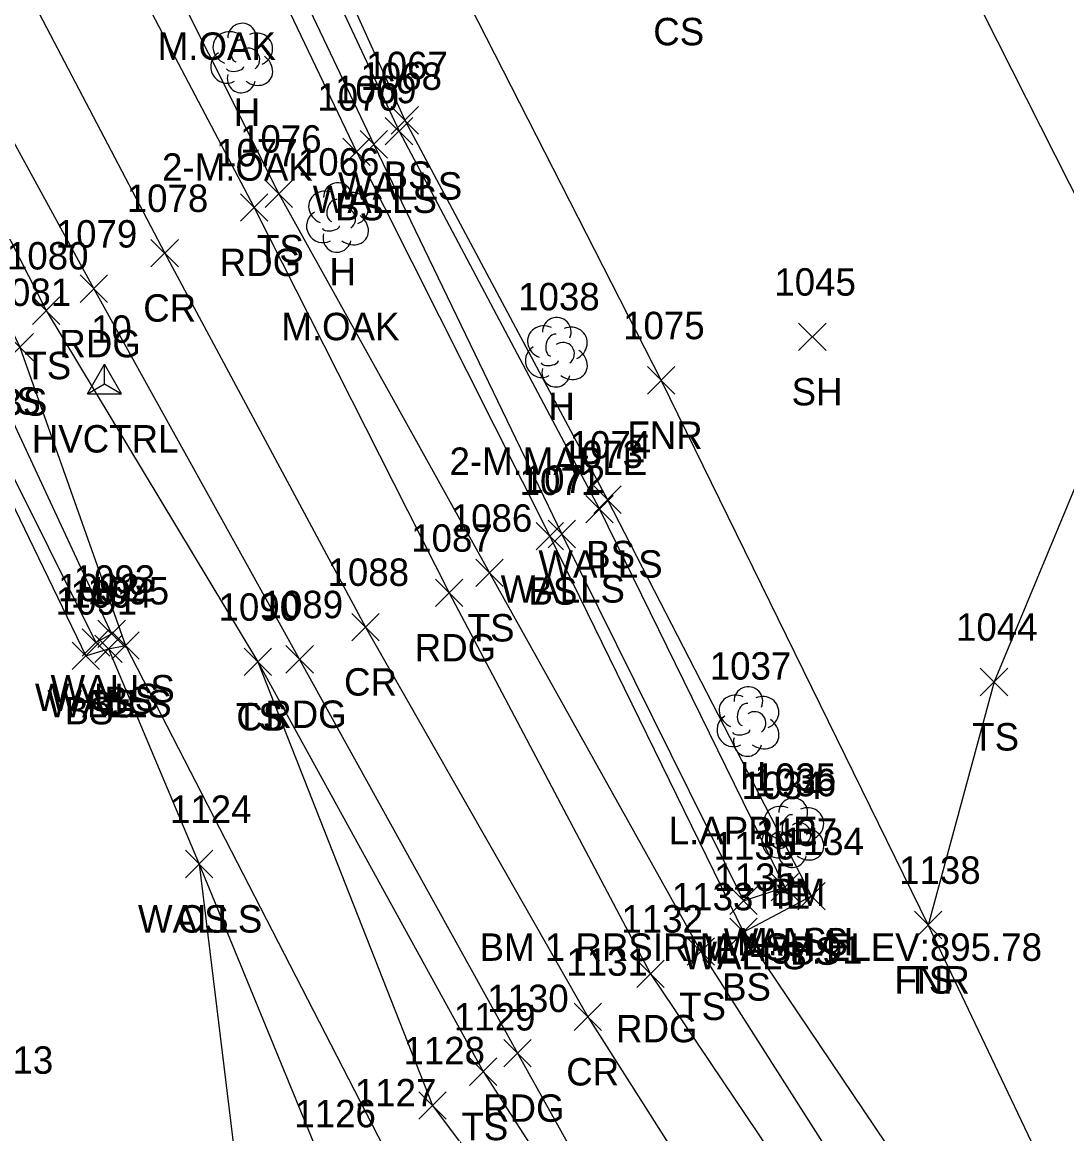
# Model space of a CAD drawing. Extents: x 1441651 to 1442140, y 243798 to 245625.
# Drawn here: x 1441948.7 to 1442024.9, y 245501.1 to 245582.1 of the extents above; entities that cross this region are included whole.
import ezdxf

# ---------------------------------------------------------------- set-up
doc = ezdxf.new("R2010")
doc.units = 0
for name, color, linetype in [('C_A', 7, 'Continuous'), ('C_C', 7, 'Continuous'), ('C_I', 7, 'Continuous'), ('CBP', 7, 'Continuous'), ('CPBM', 7, 'Continuous'), ('CPSM', 7, 'Continuous'), ('L_A', 7, 'Continuous'), ('L_C', 7, 'Continuous'), ('L_I', 7, 'Continuous'), ('L_TIC', 7, 'Continuous'), ('LELB', 7, 'Continuous'), ('LFNC', 7, 'Continuous'), ('LSOGP', 7, 'Continuous'), ('LTD', 7, 'Continuous'), ('LWS', 7, 'Continuous'), ('P_A', 7, 'Continuous'), ('P_I', 7, 'Continuous'), ('P_TIC', 7, 'Continuous'), ('PEU', 7, 'Continuous'), ('PRC', 7, 'Continuous')]:
    doc.layers.add(name, color=color, linetype=linetype)

msp = doc.modelspace()

# ---------------------------------------------------------------- linework, layer by layer
at = {"layer": 'CBP'}
for radius in [0.625, 0.0833]:
    msp.add_circle((1442003.914, 245522.51), radius, dxfattribs=at)
at = {"layer": 'CPBM'}
for p, q in [((1442004.413, 245522.213), (1442004.413, 245523.213)), ((1442004.413, 245523.213), (1442005.413, 245523.213)), ((1442005.413, 245523.213), (1442005.413, 245522.213)), ((1442004.916, 245522.713), (1442004.916, 245522.713)), ((1442004.916, 245522.713), (1442004.916, 245522.713)), ((1442005.413, 245522.213), (1442004.413, 245522.213))]:
    msp.add_line(p, q, dxfattribs=at)
at = {"layer": 'CPSM'}
for p, q in [((1441953.421, 245555.052), (1441954.671, 245557.218)), ((1441955.921, 245555.052), (1441954.671, 245557.218)), ((1441954.671, 245555.774), (1441954.671, 245557.218)), ((1441953.421, 245555.052), (1441954.671, 245555.774)), ((1441954.671, 245555.774), (1441954.671, 245555.774)), ((1441954.671, 245555.774), (1441955.921, 245555.052)), ((1441953.421, 245555.052), (1441955.921, 245555.052))]:
    msp.add_line(p, q, dxfattribs=at)
at = {"layer": 'L_TIC'}
for points in [[(1441975.585, 245573.997), (1441977.585, 245575.997)], [(1441977.585, 245573.997), (1441975.585, 245575.997)], [(1441975.154, 245573.213), (1441977.154, 245575.213)], [(1441977.154, 245573.213), (1441975.154, 245575.213)], [(1441972.054, 245571.702), (1441974.054, 245573.702)], [(1441974.054, 245571.702), (1441972.054, 245573.702)], [(1441973.311, 245572.242), (1441975.311, 245574.242)], [(1441975.311, 245572.242), (1441973.311, 245574.242)], [(1441966.384, 245568.64), (1441968.384, 245570.64)], [(1441968.384, 245568.64), (1441966.384, 245570.64)], [(1441949.412, 245560.12), (1441951.412, 245562.12)], [(1441951.412, 245560.12), (1441949.412, 245562.12)], [(1442005.303, 245558.212), (1442007.303, 245560.212)], [(1442007.303, 245558.212), (1442005.303, 245560.212)], [(1441947.491, 245557.459), (1441949.491, 245559.459)], [(1441949.491, 245557.459), (1441947.491, 245559.459)], [(1441994.271, 245555.037), (1441996.271, 245557.037)], [(1441996.271, 245555.037), (1441994.271, 245557.037)], [(1441990.363, 245546.336), (1441992.363, 245548.336)], [(1441992.363, 245546.336), (1441990.363, 245548.336)], [(1441989.775, 245545.648), (1441991.775, 245547.648)], [(1441991.775, 245545.648), (1441989.775, 245547.648)], [(1441986.155, 245543.678), (1441988.155, 245545.678)], [(1441988.155, 245543.678), (1441986.155, 245545.678)], [(1441987.023, 245543.831), (1441989.023, 245545.831)], [(1441989.023, 245543.831), (1441987.023, 245545.831)], [(1441981.753, 245540.997), (1441983.753, 245542.997)], [(1441983.753, 245540.997), (1441981.753, 245542.997)], [(1441953.048, 245535.929), (1441955.048, 245537.929)], [(1441955.048, 245535.929), (1441953.048, 245537.929)], [(1441954.19, 245536.551), (1441956.19, 245538.551)], [(1441956.19, 245536.551), (1441954.19, 245538.551)], [(1441954.19, 245536.551), (1441956.19, 245538.551)], [(1441956.19, 245536.551), (1441954.19, 245538.551)], [(1441953.957, 245535.46), (1441955.957, 245537.46)], [(1441955.957, 245535.46), (1441953.957, 245537.46)], [(1441953.957, 245535.46), (1441955.957, 245537.46)], [(1441955.957, 245535.46), (1441953.957, 245537.46)], [(1441955.206, 245535.697), (1441957.206, 245537.697)], [(1441957.206, 245535.697), (1441955.206, 245537.697)], [(1441955.206, 245535.697), (1441957.206, 245537.697)], [(1441957.206, 245535.697), (1441955.206, 245537.697)], [(1441952.315, 245534.956), (1441954.315, 245536.956)], [(1441954.315, 245534.956), (1441952.315, 245536.956)], [(1441964.846, 245534.511), (1441966.846, 245536.511)], [(1441966.846, 245534.511), (1441964.846, 245536.511)], [(1441964.846, 245534.511), (1441966.846, 245536.511)], [(1441966.846, 245534.511), (1441964.846, 245536.511)], [(1442018.558, 245533.046), (1442020.558, 245535.046)], [(1442020.558, 245533.046), (1442018.558, 245535.046)], [(1442018.558, 245533.046), (1442020.558, 245535.046)], [(1442020.558, 245533.046), (1442018.558, 245535.046)], [(1441960.569, 245519.773), (1441962.569, 245521.773)], [(1441962.569, 245519.773), (1441960.569, 245521.773)], [(1441960.569, 245519.773), (1441962.569, 245521.773)], [(1441962.569, 245519.773), (1441960.569, 245521.773)], [(1442003.296, 245518.092), (1442005.296, 245520.092)], [(1442005.296, 245518.092), (1442003.296, 245520.092)], [(1442003.296, 245518.092), (1442005.296, 245520.092)], [(1442005.296, 245518.092), (1442003.296, 245520.092)], [(1442005.245, 245517.425), (1442007.245, 245519.425)], [(1442007.245, 245517.425), (1442005.245, 245519.425)], [(1442000.283, 245517.1), (1442002.283, 245519.1)], [(1442002.283, 245517.1), (1442000.283, 245519.1)], [(1442000.278, 245514.813), (1442002.278, 245516.813)], [(1442002.278, 245514.813), (1442000.278, 245516.813)], [(1442000.278, 245514.813), (1442002.278, 245516.813)], [(1442002.278, 245514.813), (1442000.278, 245516.813)], [(1442013.76, 245515.326), (1442015.76, 245517.326)], [(1442015.76, 245515.326), (1442013.76, 245517.326)], [(1442013.76, 245515.326), (1442015.76, 245517.326)], [(1442015.76, 245515.326), (1442013.76, 245517.326)], [(1441997.178, 245513.398), (1441999.178, 245515.398)], [(1441999.178, 245513.398), (1441997.178, 245515.398)], [(1441981.294, 245504.635), (1441983.294, 245506.635)], [(1441983.294, 245504.635), (1441981.294, 245506.635)], [(1441977.601, 245502.173), (1441979.601, 245504.173)], [(1441979.601, 245502.173), (1441977.601, 245504.173)]]:
    msp.add_lwpolyline(points, dxfattribs=at)
at = {"layer": 'LELB'}
for points in [[(1441962.421, 245606.26), (1441976.585, 245574.997), (1441991.363, 245547.336), (1442006.245, 245518.425), (1442001.278, 245515.813)], [(1441958.143, 245603.853), (1441973.054, 245572.702), (1441987.155, 245544.678), (1442001.278, 245515.813), (1442017.222, 245492.134), (1442028.726, 245467.165), (1442040.19, 245452.018), (1442046.602, 245443.334), (1442055.536, 245439.064), (1442059.345, 245437.756)], [(1441951.999, 245600.361), (1441967.384, 245569.64), (1441982.753, 245541.997), (1441998.178, 245514.398), (1442013.668, 245490.085), (1442025.646, 245464.596), (1442043.563, 245442.549), (1442056.061, 245427.98)], [(1441935.553, 245590.253), (1441950.412, 245561.12), (1441965.846, 245535.511), (1441982.294, 245505.635), (1441993.222, 245488.677)], [(1441933.718, 245589.334), (1441948.491, 245558.459), (1441956.206, 245536.697), (1441975.054, 245500.102), (1441979.331, 245493.092), (1441987.533, 245478.538), (1441986.565, 245474.385), (1441981.273, 245469.984), (1441969.099, 245476.162)], [(1441929.024, 245587.875), (1441942.939, 245557.338), (1441953.315, 245535.956), (1441954.957, 245536.46), (1441956.206, 245536.697)], [(1442030.344, 245559.965), (1442019.558, 245534.046)], [(1441965.846, 245535.511), (1441978.601, 245503.173), (1441992.694, 245484.345)], [(1442019.558, 245534.046), (1442014.76, 245516.326)], [(1441961.569, 245520.773), (1441964.796, 245494.494), (1441969.099, 245476.162)]]:
    msp.add_lwpolyline(points, dxfattribs=at)
at = {"layer": 'LFNC'}
msp.add_lwpolyline([(1441970.219, 245607.538), (1441978.861, 245588.199), (1441995.271, 245556.037), (1442014.76, 245516.326), (1442024.694, 245495.45), (1442031.67, 245481.036), (1442036.993, 245470.06), (1442042.58, 245457.764), (1442044.092, 245455.722)], dxfattribs=at)
at = {"layer": 'LSOGP'}
msp.add_lwpolyline([(1442030.344, 245559.965), (1442014.55, 245591.18)], dxfattribs=at)
at = {"layer": 'LTD'}
for p, q in [((1441964.664, 245579.589), (1441964.664, 245579.589)), ((1441964.664, 245579.589), (1441964.664, 245579.589)), ((1441971.648, 245567.963), (1441971.648, 245567.963)), ((1441971.648, 245567.963), (1441971.648, 245567.963)), ((1441987.616, 245558.142), (1441987.616, 245558.142)), ((1441987.616, 245558.142), (1441987.616, 245558.142)), ((1442001.591, 245531.216), (1442001.591, 245531.216)), ((1442001.591, 245531.216), (1442001.591, 245531.216)), ((1442004.863, 245523.11), (1442004.863, 245523.11)), ((1442004.863, 245523.11), (1442004.863, 245523.11))]:
    msp.add_line(p, q, dxfattribs=at)
for centre in [(1441964.71, 245581.023), (1441971.695, 245569.397), (1441987.663, 245559.575), (1442001.637, 245532.65), (1442004.909, 245524.544)]:
    msp.add_arc(centre, 1.047, 335.52715, 180.95627, dxfattribs=at)
for centre, major_axis, ratio, start_param, end_param in [((1441963.872, 245580.256), (1.21, -0.512), 0.895232, 1.570796, 4.712389), ((1441964.455, 245580.047), (-0.208, -0.792), 0.645439, 3.141593, 6.283185), ((1441965.705, 245580.173), (-1.141, -0.483), 0.949671, 1.570796, 4.712389), ((1441965.164, 245579.423), (-0.5, 0.667), 0.989748, 3.141593, 6.283185), ((1441963.58, 245578.881), (0.584, -1.042), 0.959034, 3.141593, 6.283185), ((1441965.664, 245578.756), (-1.09, 0.792), 0.841452, 1.570796, 4.712389), ((1441964.664, 245578.089), (0.265, 1.061), 0.942809, 1.570796, 4.712389), ((1441964.205, 245578.839), (-0.625, -0.083), 0.423636, 0, 3.141593), ((1441970.856, 245568.63), (1.21, -0.512), 0.895232, 1.570796, 4.712389), ((1441972.69, 245568.547), (-1.141, -0.483), 0.949671, 1.570796, 4.712389), ((1441971.44, 245568.422), (-0.208, -0.792), 0.645439, 3.141593, 6.283185), ((1441972.148, 245567.797), (-0.5, 0.667), 0.989748, 3.141593, 6.283185), ((1441970.565, 245567.255), (0.584, -1.042), 0.959034, 3.141593, 6.283185), ((1441972.648, 245567.13), (-1.09, 0.792), 0.841452, 1.570796, 4.712389), ((1441971.19, 245567.213), (-0.625, -0.083), 0.423636, 0, 3.141593), ((1441971.648, 245566.463), (0.265, 1.061), 0.942809, 1.570796, 4.712389), ((1441986.824, 245558.808), (1.21, -0.512), 0.895232, 1.570796, 4.712389), ((1441988.657, 245558.725), (-1.141, -0.483), 0.949671, 1.570796, 4.712389), ((1441987.407, 245558.6), (-0.208, -0.792), 0.645439, 3.141593, 6.283185), ((1441988.116, 245557.975), (-0.5, 0.667), 0.989748, 3.141593, 6.283185), ((1441986.533, 245557.433), (0.584, -1.042), 0.959034, 3.141593, 6.283185), ((1441988.616, 245557.308), (-1.09, 0.792), 0.841452, 1.570796, 4.712389), ((1441987.158, 245557.391), (-0.625, -0.083), 0.423636, 0, 3.141593), ((1441987.616, 245556.642), (0.265, 1.061), 0.942809, 1.570796, 4.712389), ((1442000.799, 245531.883), (1.21, -0.512), 0.895232, 1.570796, 4.712389), ((1442002.632, 245531.8), (-1.141, -0.483), 0.949671, 1.570796, 4.712389), ((1442001.382, 245531.675), (-0.208, -0.792), 0.645439, 3.141593, 6.283185), ((1442000.507, 245530.508), (0.584, -1.042), 0.959034, 3.141593, 6.283185), ((1442002.091, 245531.05), (-0.5, 0.667), 0.989748, 3.141593, 6.283185), ((1442001.132, 245530.466), (-0.625, -0.083), 0.423636, 0, 3.141593), ((1442002.591, 245530.383), (-1.09, 0.792), 0.841452, 1.570796, 4.712389), ((1442001.591, 245529.716), (0.265, 1.061), 0.942809, 1.570796, 4.712389), ((1442004.071, 245523.777), (1.21, -0.512), 0.895232, 1.570796, 4.712389), ((1442005.904, 245523.694), (-1.141, -0.483), 0.949671, 1.570796, 4.712389), ((1442004.654, 245523.568), (-0.208, -0.792), 0.645439, 3.141593, 6.283185), ((1442003.779, 245522.402), (0.584, -1.042), 0.959034, 3.141593, 6.283185), ((1442005.363, 245522.944), (-0.5, 0.667), 0.989748, 3.141593, 6.283185), ((1442004.404, 245522.36), (-0.625, -0.083), 0.423636, 0, 3.141593), ((1442005.863, 245522.277), (-1.09, 0.792), 0.841452, 1.570796, 4.712389), ((1442004.863, 245521.61), (0.265, 1.061), 0.942809, 1.570796, 4.712389)]:
    msp.add_ellipse(centre, major_axis=major_axis, ratio=ratio, start_param=start_param, end_param=end_param, dxfattribs=at)
at = {"layer": 'LWS'}
for points in [[(1441961.452, 245605.611), (1441976.154, 245574.213), (1441990.775, 245546.648), (1442004.296, 245519.092)], [(1441959.347, 245604.671), (1441974.311, 245573.242), (1441988.023, 245544.831), (1442001.283, 245518.1), (1442004.296, 245519.092)], [(1441932.574, 245588.698), (1441945.41, 245558.535), (1441955.19, 245537.551)], [(1441929.024, 245587.875), (1441943.666, 245557.696), (1441954.048, 245536.929), (1441955.19, 245537.551)], [(1441954.957, 245536.46), (1441961.569, 245520.773), (1441970.698, 245498.575), (1441976.402, 245492.157), (1441985.367, 245476.164)]]:
    msp.add_lwpolyline(points, dxfattribs=at)
at = {"layer": 'P_TIC'}
for points in [[(1441964.584, 245567.638), (1441966.584, 245569.638)], [(1441966.584, 245567.638), (1441964.584, 245569.638)], [(1441958.061, 245564.314), (1441960.061, 245566.314)], [(1441960.061, 245564.314), (1441958.061, 245566.314)], [(1441952.89, 245561.719), (1441954.89, 245563.719)], [(1441954.89, 245561.719), (1441952.89, 245563.719)], [(1441978.812, 245539.541), (1441980.812, 245541.541)], [(1441980.812, 245539.541), (1441978.812, 245541.541)], [(1441972.709, 245537.049), (1441974.709, 245539.049)], [(1441974.709, 245537.049), (1441972.709, 245539.049)], [(1441967.906, 245534.694), (1441969.906, 245536.694)], [(1441969.906, 245534.694), (1441967.906, 245536.694)], [(1441993.499, 245511.774), (1441995.499, 245513.774)], [(1441995.499, 245511.774), (1441993.499, 245513.774)], [(1441988.919, 245508.625), (1441990.919, 245510.625)], [(1441990.919, 245508.625), (1441988.919, 245510.625)], [(1441983.797, 245505.977), (1441985.797, 245507.977)], [(1441985.797, 245505.977), (1441983.797, 245507.977)]]:
    msp.add_lwpolyline(points, dxfattribs=at)
at = {"layer": 'PEU'}
for points in [[(1441949.699, 245598.806), (1441965.584, 245568.638), (1441979.812, 245540.541), (1441994.499, 245512.774), (1442011.015, 245488.252), (1442024.854, 245464.866), (1442045.339, 245434.299), (1442053.641, 245424.38)], [(1441937.939, 245591.884), (1441953.89, 245562.719), (1441968.906, 245535.694), (1441984.797, 245506.977), (1441992.987, 245492.297), (1442013.076, 245458.975), (1442024.733, 245444.52), (1442043.134, 245414.629), (1442048.272, 245419.302), (1442053.641, 245424.38)]]:
    msp.add_lwpolyline(points, dxfattribs=at)
at = {"layer": 'PRC'}
msp.add_lwpolyline([(1441943.372, 245595.219), (1441959.061, 245565.314), (1441973.709, 245538.049), (1441989.919, 245509.625), (1442005.514, 245485.136), (1442020.379, 245462.654), (1442040.921, 245430.942), (1442048.272, 245419.302)], dxfattribs=at)

# ---------------------------------------------------------------- texts
at = {"layer": 'C_A'}
for s, p in [('HVCTRL', (1441949.364, 245550.774)), ('TIE', (1442001.993, 245517.51)), ('BM', (1442003.231, 245517.713))]:
    msp.add_text(s, height=2, dxfattribs=at).set_placement(p)
at = {"layer": 'C_C'}
for s, p in [('BM 1 RRSIR M.ASH ELEV:895.78', (1441982.034, 245513.713)), ('TIE =57.91', (1441996.811, 245513.51))]:
    msp.add_text(s, height=2, dxfattribs=at).set_placement(p)
at = {"layer": 'C_I'}
for s, p in [('10', (1441953.687, 245558.774)), ('1034', (1442001.142, 245525.51)), ('1036', (1442002.089, 245525.713))]:
    msp.add_text(s, height=2, dxfattribs=at).set_placement(p)
at = {"layer": 'L_A'}
for s, p in [('CS', (1441994.701, 245580.465)), ('H', (1441964.097, 245574.589)), ('BS', (1441975.026, 245569.997)), ('WALLS', (1441971.698, 245569.213)), ('WALLS', (1441969.854, 245568.242)), ('BS', (1441971.495, 245567.702)), ('TS', (1441965.794, 245564.64)), ('H', (1441971.081, 245562.963)), ('TS', (1441948.821, 245556.12)), ('SH', (1442004.791, 245554.212)), ('WALLS', (1441940.953, 245553.535)), ('BS', (1441946.932, 245553.459)), ('H', (1441987.049, 245553.142)), ('FNR', (1441992.806, 245551.037)), ('BS', (1441989.804, 245542.336)), ('WALLS', (1441986.319, 245541.648)), ('WALLS', (1441983.566, 245539.831)), ('BS', (1441985.596, 245539.678)), ('TS', (1441981.162, 245536.997)), ('WALLS', (1441950.734, 245532.551)), ('WALLS', (1441950.734, 245532.551)), ('WALLS', (1441949.591, 245531.929)), ('WALLS', (1441950.5, 245531.46)), ('BS', (1441951.756, 245530.956)), ('BS', (1441953.398, 245531.46)), ('BS', (1441954.647, 245531.697)), ('BS', (1441954.647, 245531.697)), ('TS', (1441964.255, 245530.511)), ('CS', (1441964.287, 245530.511)), ('TS', (1442017.967, 245529.046)), ('TS', (1442017.967, 245529.046)), ('H', (1442001.024, 245526.216)), ('H', (1442004.296, 245518.11)), ('WALLS', (1441957.112, 245515.773)), ('CS', (1441960.01, 245515.773)), ('WALLS', (1441999.839, 245514.092)), ('WALLS', (1441999.839, 245514.092)), ('WALLS', (1441996.826, 245513.1)), ('BS', (1442004.686, 245513.425)), ('BS', (1441999.719, 245510.813)), ('BS', (1441999.719, 245510.813)), ('FNR', (1442012.295, 245511.326)), ('TS', (1442013.169, 245511.326)), ('TS', (1441996.587, 245509.398)), ('TS', (1441980.704, 245500.635))]:
    msp.add_text(s, height=2, dxfattribs=at).set_placement(p)
at = {"layer": 'L_C'}
for s, p in [('M.OAK', (1441958.554, 245579.403)), ('2-M.OAK', (1441958.868, 245570.589)), ('M.OAK', (1441967.569, 245558.963)), ('2-M.MAPLE', (1441979.836, 245549.142)), ('L.APPLE', (1441995.827, 245522.216)), ('M.ASH', (1442000.815, 245514.11))]:
    msp.add_text(s, height=2, dxfattribs=at).set_placement(p)
at = {"layer": 'L_I'}
for s, p in [('1067', (1441973.766, 245577.997)), ('1068', (1441973.335, 245577.213)), ('1070', (1441970.195, 245575.702)), ('1069', (1441971.484, 245576.242)), ('1076', (1441964.557, 245572.64)), ('1066', (1441968.774, 245570.963)), ('1080', (1441947.553, 245564.12)), ('1045', (1442003.531, 245562.212)), ('1081', (1441946.286, 245561.459)), ('1038', (1441984.844, 245561.142)), ('1075', (1441992.499, 245559.037)), ('1073', (1441988.004, 245549.648)), ('1074', (1441988.592, 245550.336)), ('1071', (1441984.95, 245547.678)), ('1072', (1441985.251, 245547.831)), ('1086', (1441979.926, 245544.997)), ('1092', (1441951.276, 245539.929)), ('1093', (1441952.419, 245540.551)), ('1093', (1441952.419, 245540.551)), ('1094', (1441952.185, 245539.46)), ('1094', (1441952.185, 245539.46)), ('1095', (1441953.434, 245539.697)), ('1095', (1441953.434, 245539.697)), ('1091', (1441951.11, 245538.956)), ('1090', (1441962.988, 245538.511)), ('1090', (1441962.988, 245538.511)), ('1044', (1442016.786, 245537.046)), ('1044', (1442016.786, 245537.046)), ('1037', (1441998.819, 245534.216)), ('1035', (1442002.091, 245526.11)), ('1124', (1441959.443, 245523.773)), ('1124', (1441959.443, 245523.773)), ('1137', (1442002.17, 245522.092)), ('1137', (1442002.17, 245522.092)), ('1134', (1442004.119, 245521.425)), ('1136', (1441999.102, 245521.1)), ('1135', (1441999.152, 245518.813)), ('1135', (1441999.152, 245518.813)), ('1138', (1442012.634, 245519.326)), ('1138', (1442012.634, 245519.326)), ('1133', (1441996.052, 245517.398)), ('1129', (1441980.16, 245508.635)), ('1128', (1441976.475, 245506.173)), ('1113', (1441944.98, 245505.48)), ('1127', (1441972.928, 245503.102)), ('1126', (1441968.517, 245501.575))]:
    msp.add_text(s, height=2, dxfattribs=at).set_placement(p)
at = {"layer": 'P_A'}
for s, p in [('RDG', (1441963.073, 245563.638)), ('CR', (1441957.495, 245560.314)), ('RDG', (1441951.378, 245557.719)), ('RDG', (1441977.3, 245535.541)), ('CR', (1441972.142, 245533.049)), ('RDG', (1441966.394, 245530.694)), ('RDG', (1441991.987, 245507.774)), ('CR', (1441988.352, 245504.625)), ('RDG', (1441982.285, 245501.977))]:
    msp.add_text(s, height=2, dxfattribs=at).set_placement(p)
at = {"layer": 'P_I'}
for s, p in [('1077', (1441962.813, 245571.638)), ('1078', (1441956.29, 245568.314)), ('1079', (1441951.11, 245565.719)), ('1087', (1441977.04, 245543.541)), ('1088', (1441970.938, 245541.049)), ('1089', (1441966.127, 245538.694)), ('1132', (1441992.373, 245515.774)), ('1131', (1441988.36, 245512.625)), ('1130', (1441982.584, 245509.977))]:
    msp.add_text(s, height=2, dxfattribs=at).set_placement(p)

doc.saveas('drawing.dxf')
